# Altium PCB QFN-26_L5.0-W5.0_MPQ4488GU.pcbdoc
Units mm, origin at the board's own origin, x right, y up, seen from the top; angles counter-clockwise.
Board outline 18.63 x 18.4 mm, 2 copper layers (Top Layer, Bottom Layer), stack 0 mm thick; 1 components, 0 nets, 26 pads, 0 vias.
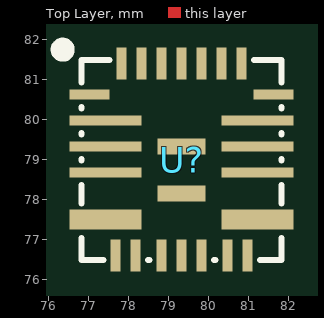
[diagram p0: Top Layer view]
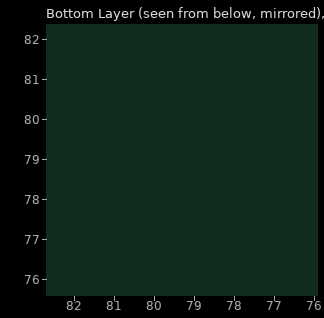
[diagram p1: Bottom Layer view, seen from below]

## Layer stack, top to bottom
Top Layer: signal copper (thickness not stored)
Bottom Layer: signal copper (thickness not stored)

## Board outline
88.475,69.85 69.85,69.85 69.85,88.25 88.475,88.25

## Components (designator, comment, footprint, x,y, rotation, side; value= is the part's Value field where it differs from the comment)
U? "" QFN-26_L5.0-W5.0_MPQ4488GU 79.325,79 r0 top

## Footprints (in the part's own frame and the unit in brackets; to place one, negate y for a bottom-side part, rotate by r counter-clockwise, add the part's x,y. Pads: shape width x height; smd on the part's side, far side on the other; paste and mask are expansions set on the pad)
QFN-26_L5.0-W5.0_MPQ4488GU [mm]
  rect 1x0.25 smd: 1(-2.3,1.625) 17(2.3,1.625)
  rect 1.8x0.25 smd: 2(-1.9,0.975) 3(-1.9,0.325) 4(-1.9,-0.325) 14(1.9,-0.325) 15(1.9,0.325) 16(1.9,0.975)
  rect 1.8x0.5 smd: 5(-1.9,-1.5) 13(1.9,-1.5)
  rect 0.25x0.8 smd: 6(-1.65,-2.4) 7(-1.15,-2.4) 8(-0.5,-2.4) 9(0,-2.4) 10(0.5,-2.4) 11(1.15,-2.4) 12(1.65,-2.4) 18(1.5,2.4) 19(1,2.4) 20(0.5,2.4) 21(0,2.4) 22(-0.5,2.4) 23(-1,2.4) 24(-1.5,2.4)
  rect 1.2x0.4 smd: 25(0,0.325) 26(0,-0.85)
  silkscreen extent -3.12,-2.51 2.5,2.9

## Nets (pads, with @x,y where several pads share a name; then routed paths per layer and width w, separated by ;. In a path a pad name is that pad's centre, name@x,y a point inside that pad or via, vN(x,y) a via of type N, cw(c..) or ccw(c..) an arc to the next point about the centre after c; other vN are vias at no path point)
pads on no net: U?.1 U?.2 U?.3 U?.4 U?.5 U?.6 U?.7 U?.8 U?.9 U?.10 U?.11 U?.12 U?.13 U?.14 U?.15 U?.16 U?.17 U?.18 U?.19 U?.20 U?.21 U?.22 U?.23 U?.24 U?.25 U?.26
